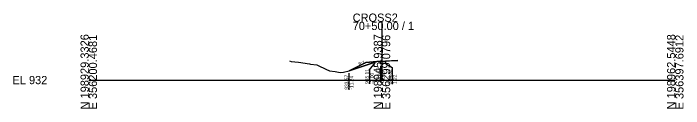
# Model space of a CAD drawing. Extents: x -26 to 203, y -10 to 14021.
# Drawn here: x -25.7 to 202.8, y 11490.3 to 11522.7 of the extents above; entities that cross this region are included whole.
import ezdxf

# ---------------------------------------------------------------- set-up
doc = ezdxf.new("R2010")
doc.units = 0
for name, color, linetype in [('Default', 7, 'Continuous'), ('P_E_XS_Ground', 7, 'Continuous'), ('P_XS', 7, 'Continuous'), ('P_XS_EAR_CommonGrnd', 7, 'Continuous'), ('P_XS_Lane', 7, 'Continuous'), ('P_XS_Rock', 7, 'Continuous')]:
    doc.layers.add(name, color=color, linetype=linetype)

msp = doc.modelspace()

# ---------------------------------------------------------------- linework, layer by layer
at = {"layer": 'Default'}
for p, q in [((100, 11500), (100, 11519.82)), ((0, 11500), (100, 11500)), ((100, 11500), (200, 11500))]:
    msp.add_line(p, q, dxfattribs=at)
at = {"layer": 'P_E_XS_Ground'}
for p, q in [((100, 11506.43), (105.22, 11506.64)), ((105.22, 11506.64), (105.34, 11506.66)), ((68.47, 11506.59), (68.98, 11506.37)), ((68.98, 11506.37), (71.54, 11506.1)), ((71.54, 11506.1), (75.25, 11505.48)), ((75.25, 11505.48), (75.56, 11505.43)), ((75.56, 11505.43), (77.72, 11505.16)), ((77.72, 11505.16), (81.28, 11503.48)), ((94.5, 11506.01), (88.76, 11503.14)), ((99.5, 11506.41), (94.5, 11506.01)), ((99.5, 11506.41), (100, 11506.43)), ((81.28, 11503.48), (81.62, 11503.35)), ((81.62, 11503.35), (82.07, 11503.17)), ((82.07, 11503.17), (84.07, 11502.86)), ((84.07, 11502.86), (85.74, 11502.58)), ((85.74, 11502.58), (86.92, 11502.63)), ((86.92, 11502.63), (88.76, 11503.14))]:
    msp.add_line(p, q, dxfattribs=at)
at = {"layer": 'P_XS'}
for p, q in [((105.22, 11506.64), (101.22, 11506.48)), ((101.22, 11506.48), (99.5, 11506.34))]:
    msp.add_line(p, q, dxfattribs=at)
at = {"layer": 'P_XS_EAR_CommonGrnd'}
msp.add_lwpolyline([(99.5, 11506.34), (98, 11506.22), (88.76, 11503.14), (94.5, 11506.01), (99.5, 11506.41), (100, 11506.43), (101.22, 11506.48), (101.22, 11505.64), (100, 11505.59), (99.5, 11505.57)], close=True, dxfattribs=at)
at = {"layer": 'P_XS_Lane'}
for p, q in [((88.76, 11503.14), (98, 11506.22)), ((99.5, 11506.34), (98, 11506.22)), ((99.5, 11505.57), (99.5, 11506.34)), ((99.5, 11505.57), (100, 11505.59)), ((101.22, 11505.64), (100, 11505.59)), ((101.22, 11506.48), (101.22, 11505.64))]:
    msp.add_line(p, q, dxfattribs=at)
at = {"layer": 'P_XS_Rock'}
for p, q in [((95.73, 11503.5), (97.71, 11505.87)), ((99.53, 11504.8), (99.53, 11499.21)), ((101.36, 11505.56), (103.52, 11504.24)), ((88.74, 11502.32), (88.74, 11496.72)), ((95.73, 11503.5), (95.73, 11498.7)), ((103.52, 11504.24), (103.52, 11498.65))]:
    msp.add_line(p, q, dxfattribs=at)

# ---------------------------------------------------------------- texts
at = {"layer": 'Default'}
for s, p in [('CROSS2', (90, 11519.82)), ('70+50.00 / 1', (90, 11517.02)), ('EL 932', (-26, 11498.6))]:
    msp.add_text(s, height=2.8, dxfattribs=at).set_placement(p)
for s, p in [('N 198929.3326', (0, 11490)), ('E 356200.4681', (2.8, 11490)), ('N 198945.9387', (100, 11490)), ('E 356299.0796', (102.8, 11490)), ('N 198962.5448', (200, 11490)), ('E 356397.6912', (202.8, 11490))]:
    msp.add_text(s, height=2.8, rotation=90, dxfattribs=at).set_placement(p)
at = {"layer": 'P_XS_Rock'}
for s, rotation, p in [('6:1', 18.4349, (92.2, 11504.85)), ('935.11', 90, (95.48, 11498.7)), ('-2.00', 90, (97.18, 11498.7)), ('934.79', 90, (99.28, 11499.21)), ('-0.50', 90, (100.98, 11499.21)), ('934.82', 90, (103.27, 11498.65)), ('933.57', 90, (88.49, 11496.72)), ('-11.24', 90, (90.19, 11496.72)), ('1.22', 90, (104.97, 11498.65))]:
    msp.add_text(s, height=1.2, rotation=rotation, dxfattribs=at).set_placement(p)

doc.saveas('drawing.dxf')
